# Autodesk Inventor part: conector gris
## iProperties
Created: 2008-01
Part Number: conector gris
Document SubType Name: Modeling
Designer: eruiz-tagle
Mass: 0.0579601 g
Surface Area: 4.16337 cm^2
Volume: 0.0579601 cm^3
Density: 1 g/cm^3
Author: eruiz-tagle
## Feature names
1. Revolution1
2. Fillet1
3. Extrusion1
4. Mirror1
